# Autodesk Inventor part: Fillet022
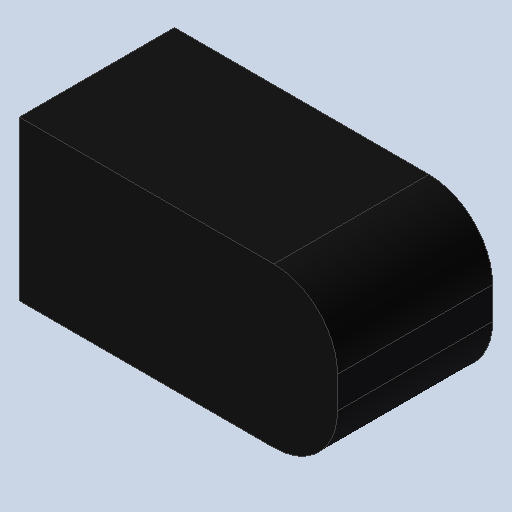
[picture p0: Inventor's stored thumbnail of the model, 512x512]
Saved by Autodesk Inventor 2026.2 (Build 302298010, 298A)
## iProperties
Created: 2026-10
Part Number: Fillet022
Material: Générique
Document SubType Name: Modeling
Designer: mel
Density: 1 g/cm^3
Appearance: Par défaut
Author: mel
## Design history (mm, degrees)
feature "Base1"
node "Solide1"
